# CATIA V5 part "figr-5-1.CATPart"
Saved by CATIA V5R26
Part number: Part1
Bounding box of the stored display mesh (mm): x -23 to 23, y -104 to 104, z 0 to 68
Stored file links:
  D:\_Deepak\CATIA\CATIA V5-6R2016_Deepak\Resources\Part files\Partfiles\c05_catia_v5_6r2016_prt\figr-5-1.CATPart
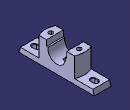
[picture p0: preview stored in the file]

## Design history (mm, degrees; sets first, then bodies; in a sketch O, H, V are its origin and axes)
Sketch1 on yz-plane, origin (0, 0, 0), H (0, 1, 0), V (0, 0, 1)
  line L1 (0, 0) -> (104, 0)
  point P1 (104, 0)
  line L2 (104, 0) -> (100, 14)
  point P2 (100, 14)
  line L3 (100, 14) -> (54, 14)
  point P3 (54, 14)
  line L4 (54, 14) -> (54, 68)
  point P4 (54, 68)
  line L5 (54, 68) -> (28, 68)
  point P5 (28, 68)
  line L6 (28, 68) -> (28, 52)
  point P6 (28, 52)
  line L7 (28, 52) -> (23.6643, 52)
  axis line L8 (0, 0) -> (0, 150)
  point P8 (0, 0)
  construction line L9 through (0, 0) direction (-1, 0)
  construction line L10 through (0, 0) direction (0, 1)
  point P13 (-104, 0)
  point P14 (-100, 14)
  point P15 (-54, 14)
  point P16 (-54, 68)
  point P17 (-28, 68)
  point P18 (-28, 52)
  line L11 (0, 0) -> (-104, 0)
  line L12 (-104, 0) -> (-100, 14)
  line L13 (-100, 14) -> (-54, 14)
  line L14 (-54, 14) -> (-54, 68)
  line L15 (-54, 68) -> (-28, 68)
  line L16 (-28, 68) -> (-28, 52)
  line L17 (-28, 52) -> (-23.6643, 52)
  arc A1 centre (0, 48) radius 24 from (-23.6643, 52) to (23.6643, 52) ccw
  point P19 (0, 48)
  point P20 (13.2665, 68)
  distance P1 P13 = 208
  length L2 V = 14
  length L2 H = 4
  distance L4 L14 = 108
  distance L16 L6 = 56
  distance L1 L5 = 68
  length L6 = 16
  distance P19 L7 = 4
  radius A1 = 24
  horizontal: L1 H, L3 H, L5 H, L7 H
  vertical: L4 V, L6 V, L8 V
  symmetry: O P8 L8, H L9 L8, V L10 L8, P1 P13 L8, P2 P14 L8, P3 P15 L8, P4 P16 L8, P5 P17 L8, P6 P18 L8, L1 L11 L8, L2 L12 L8, L3 L13 L8, L4 L14 L8, L5 L15 L8, L6 L16 L8, L7 L17 L8
  coincidence: P19 L8, A1 P20, P20 L5, O P8
Pad1: profile Sketch1, direction (1, 0, 0), length 23, mirrored extent
Body1 (main body)
  Sketch2 on face of Pad1, origin (0, 0, 68), H (1, 0, 0), V (0, 1, 0)
    arc A1 centre (0, 0) radius 54 from (-23, 48.8569) to (23, 48.8569) cw
    point P1 (0, 0)
    point P2 (-23, 48.8569)
    point P3 (23, 48.8569)
    reference projected line E1 (23, 54) -> (23, 28) from edge [face of Pad1 | face of Pad1]
    reference projected line E2 (-23, 54) -> (-23, 28) from edge [face of Pad1 | face of Pad1]
    reference projected line E3 (-23, 54) -> (23, 54) from edge [face of Pad1 | face of Pad1]
    axis line L1 (-38.3733, 0) -> (57.2772, 0)
    point P4 (-38.3733, 0)
    point P6 (-23, -48.8569)
    point P7 (23, -48.8569)
    arc A2 centre (0, 0) radius 54 from (-23, -48.8569) to (23, -48.8569) ccw
    line L2 (-23, 48.8569) -> (-23, -48.8569)
    point P9 (-23, -48.8569)
    line L3 (23, 48.8569) -> (23, -48.8569)
    coincidence: P3 E1, P2 E2, P1 O, P4 H, P9 P6
    tangency: A1 E3
    horizontal: L1 H
    symmetry: P2 P6 L1, P3 P7 L1, A1 A2 L1
    vertical: L2 V, L3 V
  Pocket1: profile Sketch2, direction (0, 0, -1), up to face of Pad1, outer side
  Sketch3 on face of Pad1, origin (0, 0, 0), H (1, 0, 0), V (0, -1, 0)
    line L1 (-13, 52) -> (13, 52)
    line L2 (13, 52) -> (13, 26)
    line L3 (13, 26) -> (-13, 26)
    line L4 (-13, 26) -> (-13, 52)
    axis line L5 (13, 26) -> (-13, 52)
    point P5 (0, 39)
    length L2 = 26
    length L1 = 26
    distance P5 O H = 0
    distance P5 H = 39
    horizontal: L1 H, L3 H
    vertical: L2 V, L4 V
    midpoint: P5 L5
  Pocket2: profile Sketch3, direction (0, 0, 1), length 10
  Sketch4 on face of Pocket2, origin (0, -39, 10), H (1, 0, 0), V (0, -1, 0)
    point P1 (0, 0)
    reference projected point E1 (0, 0) from vertex of Sketch7
    coincidence: E1 P1
  Hole1: placed by Sketch4, at (0, -39, 10) direction (0, 0, 1), diameter 12, through (limit type 3)
  Sketch5 on face of Pad1, origin (0, 0, 14), H (1, 0, 0), V (0, 1, 0)
    construction line L1 (0, -85) -> (0, -77)
    point P1 (0, -85)
    line L2 (-6, -85) -> (-6, -77)
    line L3 (6, -77) -> (6, -85)
    arc A1 centre (0, -77) radius 6 from (-6, -77) to (6, -77) cw
    arc A2 centre (0, -85) radius 6 from (6, -85) to (-6, -85) cw
    point P7 (0, -81)
    distance A1 A2 = 20
    distance L3 L2 = 12
    distance P7 H = 81
    coincidence: P1 V
    vertical: L1 V
    tangency: A1 L2, A2 L2, A1 L3, A2 L3
    parallelism: L1 L2
    midpoint: P7 L1
  Pocket3: profile Sketch5, direction (0, 0, -1), through (limit type 3)
  Chamfer1: length 1.5, angle 45, on 1 edge
  Sketch6 on yz-plane, origin (0, 0, 0), H (0, 1, 0), V (0, 0, 1)
    axis line L1 (0, 0) -> (0, 35.393)
    reference projected arc E1 centre (0, 48) radius 24 from (-23.6643, 52) to (23.6643, 52) ccw from edge [face of Pad1 | face of Pad1]
    projected arc E2 centre (0, 48) radius 24 from (0, 24) to (4, 24.3357) ccw from edge [face of Pad1 | face of Pad1]
    point P4 (4, 24.3357)
    line L2 (4, 24.3357) -> (4, 16)
    line L3 (4, 16) -> (0, 16)
    point P6 (0, 16)
    line L4 (0, 16) -> (0, 24)
    point P7 (0, 24)
    point P8 (0, 24)
    radius about axis L2 L1 = 4
    distance E1 L3 = 8
    vertical: L1 V, L2 V, L4 V
    coincidence: P4 E1, P6 L1, P7 E1, L1 P8, P7 P8
    horizontal: L3 H
  Groove1: profile Sketch6, axis Sketch6.L1, angle 360
  Mirror1: of Pocket2, Sketch3, Hole1, Pocket3, Sketch5, Chamfer1, about zx-plane
  Sketch7 on face of Pocket2, origin (0, 0, 10), H (1, 0, 0), V (0, -1, 0)
    point P1 (0, 39)
    axis line L1 (13, 26) -> (-13, 52)
    point P2 (13, 26)
    point P3 (-13, 52)
    reference projected point E1 (13, 26) from vertex [face of Pocket2 | face of Pad1 | face of Pocket2]
    reference projected point E2 (-13, 52) from vertex [face of Pocket2 | face of Pad1 | face of Pocket2]
    coincidence: P1 V, L1 P1, E1 P2, P3 E2
    midpoint: P1 L1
